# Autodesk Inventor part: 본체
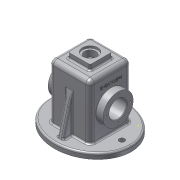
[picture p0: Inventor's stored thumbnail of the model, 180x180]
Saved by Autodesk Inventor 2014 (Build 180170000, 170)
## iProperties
Created: 2017-07
Part Number: 본체
Material: 알루미늄 6061
Document SubType Name: Modeling
Designer: user
Density: 2.71 g/cm^3
Appearance: 알루미늄 - 평지
Mass: 957.949 g
Surface Area: 976.832 cm^2
Volume: 353.487 cm^3
Author: user
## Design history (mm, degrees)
sketch "스케치1"
  geometry: L1 (0, 0)-(-75, 0); L2 (-75, 0)-(-75, 75); L3 (-75, 75)-(0, 75); L4 (0, 75)-(0, 0)
  constraints: 8 end point, 2 parallel, 1 horizontal, 1 perpendicular
  dimensions: "d0" = 75 distance of L2.end L3.end; "d1" = 75 distance of L1.end L2.end
extrude "돌출1" new body sketch "스케치1" distance "d2" = 100; taper "d3" = 0 deg
sketch "스케치2"
  geometry: L1 (0, 0)-(75, 0) reference; L2 (37.5, 37.5)-(112.5, 37.5); L3 (37.5, 37.5)-(37.5, 102.5); 1 other entity
  constraints: 4 end point, 2 horizontal, 1 vertical, 4 other
  dimensions: "d4" = 65 distance of L2.start L3.end; "d5" = 75 distance of L2.start L2.end
extrude "돌출2" join sketch "스케치2" distance "d6" = 10; taper "d7" = 0 deg
node "작업 평면1"
sketch "스케치4"
  geometry: L1 (17.5, -17.5)-(57.5, -17.5); L2 (57.5, -17.5)-(57.5, -57.5); L3 (57.5, -57.5)-(17.5, -57.5); L4 (17.5, -57.5)-(17.5, -17.5); L5 (17.5, -17.5)-(57.5, -57.5); L6 (57.5, -17.5)-(17.5, -57.5); 1 further point
  constraints: 12 end point, 2 midpoint, 2 parallel, 1 horizontal, 1 perpendicular
  dimensions: "d14" = 40 distance of L2.end L3.end; "d15" = 40 distance of L1.end L2.end
extrude "돌출4" join sketch "스케치4" distance "d16" = 10; taper "d17" = 0 deg
node "작업 평면2"
sketch "스케치5"
  geometry: 1 further point
sketch "스케치6"
  geometry: L1 (-27.5, -110)-(102.5, -110) reference; L2 (75, -100)-(75, 0) reference; C1 r 27.5 at (38, -55)
  constraints: 1 centre point
  dimensions: "d19" = 55 diameter of C1; "d20" = 55 distance from line of L1 C1.centre; "d21" = 37 distance from line of L2 C1.centre
extrude "돌출5" join sketch "스케치6" distance "d22" = 100; taper "d23" = 0 deg
sketch "스케치7"
  geometry: C1 r 27.5 at (0, 0) reference; C2 r 16 at (0, 0); 1 further point
  constraints: 1 centre point, 1 coincident
  dimensions: "d24" = 32 diameter of C2
extrude "돌출6" cut sketch "스케치7" stored distance "d25" = 100; taper "d26" = 0 deg
node "작업 평면3"
sketch "스케치8"
  geometry: L1 (0, 75)-(100, 75) reference; L2 (0, 0)-(100, 0) reference; L3 (0, -27.5)-(0, 102.5) reference; L4 (70.189, 75)-(0, 92.5); L5 (0, 92.5)-(0, 102.5); L6 (0, 102.5)-(35.183, 102.5)
  constraints: 6 end point, 2 point on line, 1 collinear, 1 perpendicular
  dimensions: "d27" = 10 distance of L4.end L3.end; "d28" = 14 deg angle of L4 L6
feature "리브1" sketch "스케치8" dims "d29" = 1, "d30" = 10, "d31" = 0, "d32" = 0, "d33" = 1, "d34" = 1
node "작업 평면4"
sketch "스케치9"
  geometry: C1 r 14 at (37.5, -37.5); 1 further point
  constraints: 1 centre point
  dimensions: "d35" = 28 diameter of C1
extrude "돌출7" cut sketch "스케치9" distance "d36" = 4; taper "d37" = 0 deg
sketch "스케치10"
  geometry: C1 r 14 at (0, 0) reference; C2 r 10.5 at (0, 0); 1 further point
  constraints: 1 centre point, 1 coincident
  dimensions: "d38" = 21 diameter of C2
extrude "돌출8" cut sketch "스케치10" stored distance "d39" = 4; taper "d40" = 0 deg
sketch "스케치11"
  geometry: C1 r 5 at (95.5, -37.5); C2 r 5 at (-20.5, -37.5); 1 further point; 1 other entity
  constraints: 2 centre point, 1 horizontal alignment, 1 other
  dimensions: "d41" = 10 diameter of C1; "d42" = 10 diameter of C2; "d43" = 58 distance of point (37.5, -37.5) C2.centre; "d44" = 58 distance of C1.centre point (37.5, -37.5)
extrude "돌출9" cut sketch "스케치11" stored distance "d45" = 4; taper "d46" = 0 deg
node "작업 평면5"
fillet "모깎기1" dims "d55" = 8
fillet "모깎기2" dims "d56" = 8
fillet "모깎기3" dims "d57" = 3
fillet "모깎기4" dims "d58" = 3
node "작업 평면6"
sketch "스케치13"
  geometry: L1 (-32.5, -67.189)-(-32.5, 21.811) reference; L2 (-24.5, 29.811)-(34.5, 29.811) reference; L3 (42.5, 21.811)-(42.5, -67.189) reference; L4 (34.5, 24.811)-(-24.5, 24.811); L5 (-70, -80.189)-(80, -80.189) reference; L6 (55.5, 2.311)-(42.5, 2.311) reference; L7 (55.5, -52.689)-(42.5, -52.689) reference; L8 (42.5, -52.689)-(24.205, -52.689); L9 (37.5, -52.689)-(30.5, -45.689); L10 (42.5, 2.311)-(26.221, 2.311); L11 (37.5, 2.311)-(30.5, -4.689); L12 (30.5, -4.689)-(30.5, -45.689); L13 (37.5, -80.189)-(37.5, -52.689); L14 (37.5, 2.311)-(37.5, 21.811); L15 (5, 24.811)-(5, -80.189); L16 (-27.5, 2.311)-(-20.5, -4.689); L17 (-20.5, -4.689)-(-20.5, -45.689); L18 (-27.5, -52.689)-(-20.5, -45.689); L19 (-27.5, -80.189)-(37.5, -80.189); L20 (-27.5, 21.811)-(-27.5, 2.311); L21 (-27.5, -52.689)-(-27.5, -80.189); A1 r 8 centre (-24.5, 21.811) between (-24.5, 29.811) and (-32.5, 21.811) reference; A2 r 8 centre (34.5, 21.811) between (42.5, 21.811) and (34.5, 29.811) reference; A3 r 3 centre (34.5, 21.811) between (37.5, 21.811) and (34.5, 24.811); A4 r 3 centre (-24.5, 21.811) between (-24.5, 24.811) and (-27.5, 21.811); 1 further point
  constraints: 30 end point, 4 point on circle, 4 point on line, 4 symmetric about line, 3 perpendicular, 2 centre point, 2 midpoint, 1 collinear, 1 parallel, 2 other
  dimensions: "d61" = 7 horizontal distance of L9.start L9.end; "d62" = 7 horizontal distance of L11.start L11.end
extrude "돌출11" cut sketch "스케치13" stored distance "d63" = 64; taper "d64" = 0 deg
fillet "모깎기5" dims "d65" = 0.5
node "작업 평면7"
fillet "모깎기6" dims "d66" = 3
fillet "모깎기7" dims "d67" = 3
chamfer "모따기1" distance "d68" = 1; stored, may be unused: second distance "d69" = 2, angle "d70" = 45 deg
sketch "스케치14" dims "d74" = 45
  geometry: L1 (0, 0)-(0, 22.5); C1 r 17 at (0, 0) reference; 2 further points
  constraints: 2 coincident, 2 end point, 1 vertical, 1 vertical alignment, 2 other
hole "구멍1" sketch "스케치14" at (0, 22.5) diameter "d75" = 3.242; stored, may be unused: countersink angle "d79" = 90 deg, drill point angle "d81" = 118 deg; dims "d76" = 8, "d77" = 4, "d78" = 2, "d80" = 10
sketch "스케치15" dims "d85" = 45
  geometry: L1 (0, 0)-(0, 22.5); C1 r 17 at (0, 0) reference; 2 further points
  constraints: 2 coincident, 2 end point, 1 vertical, 1 vertical alignment, 2 other
hole "구멍2" sketch "스케치15" at (0, 22.5) diameter "d86" = 3.242; stored, may be unused: countersink angle "d90" = 90 deg, drill point angle "d92" = 118 deg; dims "d87" = 8, "d88" = 4, "d89" = 2, "d91" = 10
fillet "모깎기8" dims "d96" = 3
sketch "스케치16"
  geometry: L1 (12.5, 18)-(46.5, 18) reference; L2 (67, -89)-(67, 0) reference; 2 further points
  constraints: 1 other
  dimensions: "d97" = 30 distance from line of L1 point (30, -12); "d98" = 37 distance from line of L2 point (30, -12)
feature "엠보싱1" sketch "스케치16" dims "d14" = 40, "d15" = 40, "d99" = 0.5, "d100" = 0
fillet "모깎기9" dims "d101" = 0.5
node "솔리드1"
mirror "대칭1"
pattern_circular "원형 패턴1" dims angle "d83" = 360 deg
pattern_circular "원형 패턴2" dims angle "d94" = 360 deg
other parameters: "d8" = 13, "d18" = 13, "d50" = 135 deg, "d59" = 5, "d60" = 135 deg
